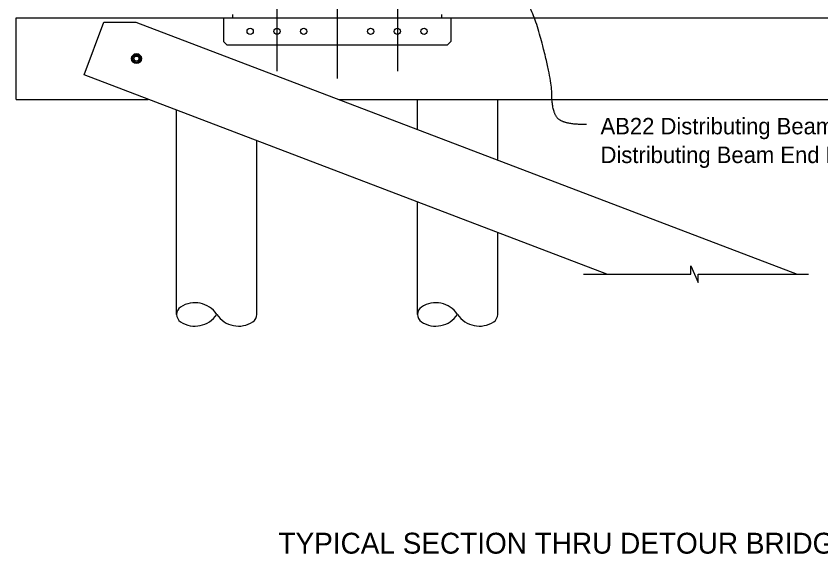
# Model space of a CAD drawing. Extents: x -4.4 to 30.2, y 1.2 to 17.8.
# Drawn here: x 1.51 to 9.03, y 3.67 to 8.76 of the extents above; entities that cross this region are included whole.
import ezdxf

# ---------------------------------------------------------------- set-up
doc = ezdxf.new("R2010")
doc.units = 0
for name, color, linetype in [('CL_Minor', 7, 'Continuous'), ('Dimension', 7, 'Continuous'), ('SteelMisc', 7, 'Continuous'), ('Symbols', 7, 'Continuous'), ('TextStructures', 7, 'Continuous'), ('Wood', 7, 'Continuous')]:
    doc.layers.add(name, color=color, linetype=linetype)

msp = doc.modelspace()

# ---------------------------------------------------------------- linework, layer by layer
at = {"layer": 'CL_Minor'}
for p, q in [((3.944, 17.6955), (3.944, 8.2442)), ((5.0694, 16.9098), (5.0694, 8.2442)), ((4.5066, 16.5378), (4.5066, 8.1779))]:
    msp.add_line(p, q, dxfattribs=at)
at = {"layer": 'Dimension'}
msp.add_open_spline([(6.8386, 7.7455), (6.5998, 7.7455), (6.513, 7.8927), (6.513, 8.1724), (6.2959, 8.9803), (5.8761, 9.2268), (5.2682, 9.4182)], degree=2, dxfattribs=at)
at = {"layer": 'SteelMisc'}
for p, q in [((3.2586, 8.7452), (26.0322, 8.7452)), ((3.4438, 8.7452), (3.4438, 8.5227)), ((3.5298, 8.777), (3.5298, 8.7452)), ((5.4836, 8.777), (5.4836, 8.7452)), ((5.5697, 8.7452), (5.5697, 8.5227)), ((3.4438, 8.5227), (3.4751, 8.4909)), ((5.5384, 8.4909), (5.5697, 8.5227)), ((3.4751, 8.4909), (5.5384, 8.4909))]:
    msp.add_line(p, q, dxfattribs=at)
msp.add_lwpolyline([(2.6665, 8.3845), (2.6665, 8.3428), (2.6309, 8.3219), (2.5954, 8.3428), (2.5954, 8.3845), (2.6309, 8.4054)], close=True, dxfattribs=at)
for centre, major_axis in [((3.6938, 8.618), (0, 0.0298)), ((3.944, 8.618), (0, 0.0298)), ((4.1941, 8.618), (0, 0.0298)), ((4.8194, 8.618), (0, -0.0298)), ((5.0694, 8.618), (0, -0.0298)), ((5.3196, 8.618), (0, -0.0298)), ((2.6309, 8.3637), (0, 0.0467)), ((2.6309, 8.3637), (0, 0.0362)), ((2.6309, 8.3637), (0, 0.0238))]:
    msp.add_ellipse(centre, major_axis=major_axis, ratio=0.983193, dxfattribs=at)
at = {"layer": 'Symbols'}
msp.add_lwpolyline([(6.8103, 6.3472), (7.8132, 6.3472), (7.8132, 6.426), (7.8807, 6.2683), (7.8807, 6.3472), (8.9142, 6.3472)], dxfattribs=at)
at = {"layer": 'Wood'}
for p, q in [((1.5055, 7.9821), (1.5055, 8.7452)), ((1.5055, 8.7452), (14.6356, 8.7452)), ((2.1422, 8.2105), (2.3247, 8.7055)), ((2.3247, 8.7055), (2.6251, 8.7055)), ((2.6251, 8.7055), (8.8081, 6.3472)), ((7.0275, 6.3472), (2.1422, 8.2105)), ((1.5055, 7.9821), (2.741, 7.9821)), ((4.5217, 7.9821), (13.627, 7.9821)), ((5.257, 7.7016), (5.257, 7.9821)), ((6.0073, 7.4155), (6.0073, 7.9821)), ((3.0061, 5.9699), (3.0061, 7.881)), ((3.7564, 5.9699), (3.7564, 7.5948)), ((5.257, 5.9699), (5.257, 7.0225)), ((6.0073, 5.9699), (6.0073, 6.7363))]:
    msp.add_line(p, q, dxfattribs=at)
for centre, major_axis, start_param, end_param in [((3.1776, 5.8284), (0, 0.251), 5.311474, 6.859887), ((5.4285, 5.8284), (0, 0.251), 5.311474, 6.859887), ((3.0864, 5.9699), (0, 0.0817), 0.569243, 1.570759), ((5.3373, 5.9699), (0, 0.0817), 0.569243, 1.570759), ((3.0864, 5.9699), (0, 0.0817), 1.570759, 2.57235), ((3.1776, 6.1114), (0, 0.251), 2.564849, 4.113262), ((3.585, 6.1113), (0, -0.2507), 5.311304, 6.859717), ((3.676, 5.9699), (0, 0.0817), 3.710836, 4.712426), ((5.3373, 5.9699), (0, 0.0817), 1.570759, 2.57235), ((5.4285, 6.1114), (0, 0.251), 2.564849, 4.113262), ((5.8359, 6.1113), (0, -0.2507), 5.311304, 6.859717), ((5.9269, 5.9699), (0, 0.0817), 3.710836, 4.712426)]:
    msp.add_ellipse(centre, major_axis=major_axis, ratio=0.983193, start_param=start_param, end_param=end_param, dxfattribs=at)

# ---------------------------------------------------------------- texts
at = {"layer": 'Dimension'}
for s, p in [('AB22 Distributing Beams with AB23 ', (6.9689, 7.6547)), ('Distributing Beam End Frame (Typ.)', (6.9689, 7.3861))]:
    msp.add_text(s, height=0.153845, dxfattribs=at).set_placement(p)
at = {"layer": 'TextStructures'}
msp.add_text('TYPICAL SECTION THRU DETOUR BRIDGE AT INTERIOR BENTS (TYPICAL SECTION AT END BENTS SIMILAR WITHOUT DISTRIBUTING BEAMS)', height=0.195359, dxfattribs=at).set_placement((3.9583, 3.7318))

doc.saveas('drawing.dxf')
